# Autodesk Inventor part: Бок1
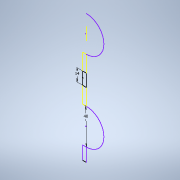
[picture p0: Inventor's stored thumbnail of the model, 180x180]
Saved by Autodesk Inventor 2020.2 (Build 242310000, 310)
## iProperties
Created: 2020-04
Part Number: Бок1
Material: Типовые
Document SubType Name: Modeling
Designer: Алексей
Density: 1 g/cm^3
Appearance: По умолчанию
Author: Алексей
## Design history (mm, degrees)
sketch "Эскиз1"
  geometry: L1 (0, 0)-(0, -51) reference; L2 (0, -51)-(4, -51) reference; L3 (4, 0)-(4, -51) reference; L4 (0, 0)-(4, 0) reference; L5 (4, -18.5)-(0, -18.5); L6 (0, -18.5)-(0, -32.5); L7 (0, -32.5)-(4, -32.5); L8 (4, -32.5)-(4, -18.5); L9 (4, -106)-(4, -91); L10 (4, -91)-(0, -91); L11 (0, -91)-(0, -106); L12 (0, -106)-(4, -106); L13 (0, -106)-(4, -106) reference; L14 (0, -51)-(4, -51) reference; L15 (0, 0)-(0, -51) reference; L16 (4, 27)-(4, 13) reference; L17 (4, 27)-(4, 13) reference; A1 r 20 centre (4, -71) between (4, -91) and (4, -51); A2 r 19.979 centre (4, 19.979) between (4, 0) and (3.976, 39.958); 1 further point
  constraints: 17 end point, 4 point on circle, 3 perpendicular, 2 centre point, 2 horizontal, 2 midpoint, 2 parallel, 2 point on line, 1 collinear, 1 tangent, 1 vertical
  dimensions: "d0" = 14 distance between parallel lines of L7 L5; "d1" = 40 diameter of A1
  node "Ссылка1"
  node "Ссылка2"
  node "Ссылка3"
  node "Ссылка4"
  node "Ссылка5"
  node "Ссылка6"
